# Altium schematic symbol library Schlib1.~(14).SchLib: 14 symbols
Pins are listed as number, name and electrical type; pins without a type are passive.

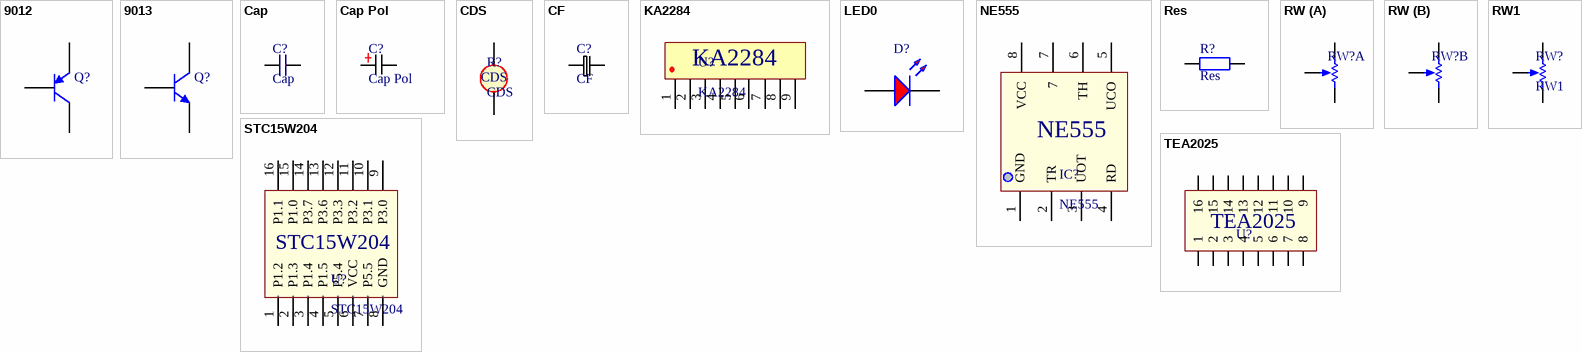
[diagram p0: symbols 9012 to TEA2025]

## 9012
designator Q?  (value not drawn)
PNP General Purpose Amplifier
footprint T092
pins: 1 E, 2 B, 3 C

## 9013
designator Q?  (value not drawn)
NPN General Purpose Amplifier
footprint T092
pins: 1 E, 2 B, 3 C

## Cap
designator C?
footprint RAD0.1
pins: 1, 2

## Cap Pol
designator C?
footprint CF0.1
pins: 1, 2

## CDS
designator R?
footprint CDS
pins: 1, 2

## CF
designator C?
footprint CF0.1
pins: 1, 2

## KA2284
designator U?
footprint SIP9
pins: 1, 2, 3, 4, 5, 6, 7, 8, 9

## LED0
designator D?  (value not drawn)
footprint LED
pins: 1 A, 2 K

## NE555
designator IC?
footprint DIP-8 (DIP; 8 Leads; Row Spacing 7.62 mm; Pitch 2.54 mm)
pins: 1 GND, 2 TR, 3 UOT, 4 RD, 5 UCO, 6 TH, 7, 8 VCC

## Res
designator R?
Resistor; Value: 1K
footprint AXIAL-0.3 (Axial Device, Thru-Hole; 2 Leads; 0.3 in Pin Spacing)
pins: 1, 2

## RW
designator RW?  (value not drawn)
footprint RW
part A pins: 1 TOP, 2 TAP, 3 BOT
part B pins: 4 TOP, 5 TAP, 6 BOT

## RW1
designator RW?
footprint RW1
pins: 1 TOP, 2 TAP, 3 BOT

## STC15W204
designator U?
footprint SOP16 - duplicate
pins: 1 P1.2, 2 P1.3, 3 P1.4, 4 P1.5, 5 P5.4, 6 VCC, 7 P5.5, 8 GND, 9 P3.0, 10 P3.1, 11 P3.2, 12 P3.3, 13 P3.6, 14 P3.7, 15 P1.0, 16 P1.1

## TEA2025
designator U?  (value not drawn)
footprint DIP16
pins: 1, 2, 3, 4, 5, 6, 7, 8, 9, 10, 11, 12, 13, 14, 15, 16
